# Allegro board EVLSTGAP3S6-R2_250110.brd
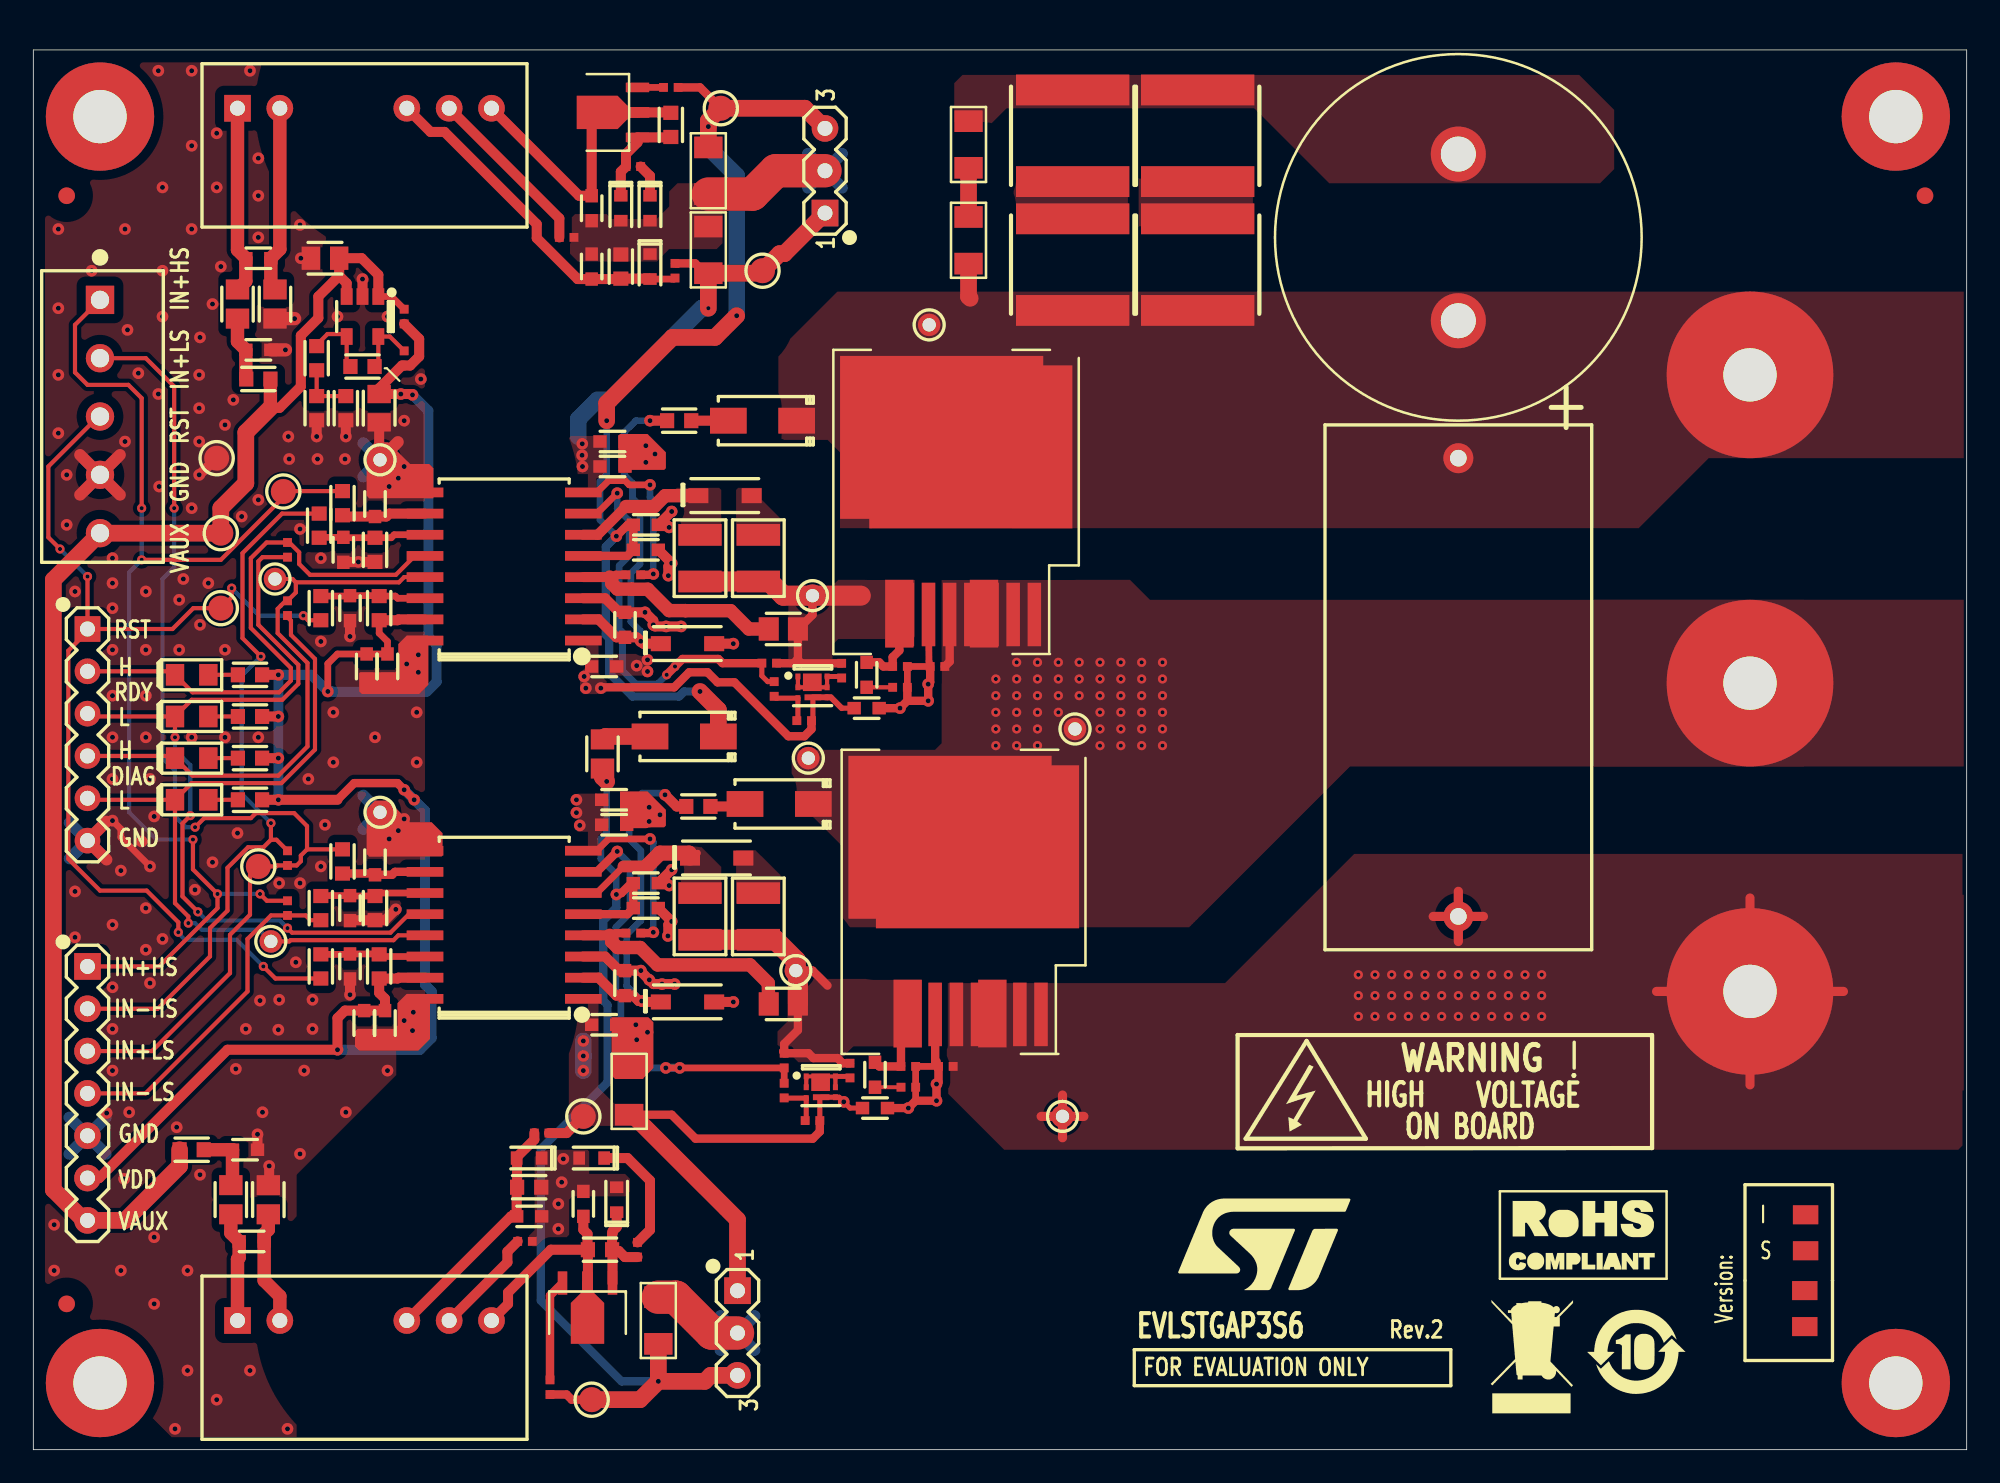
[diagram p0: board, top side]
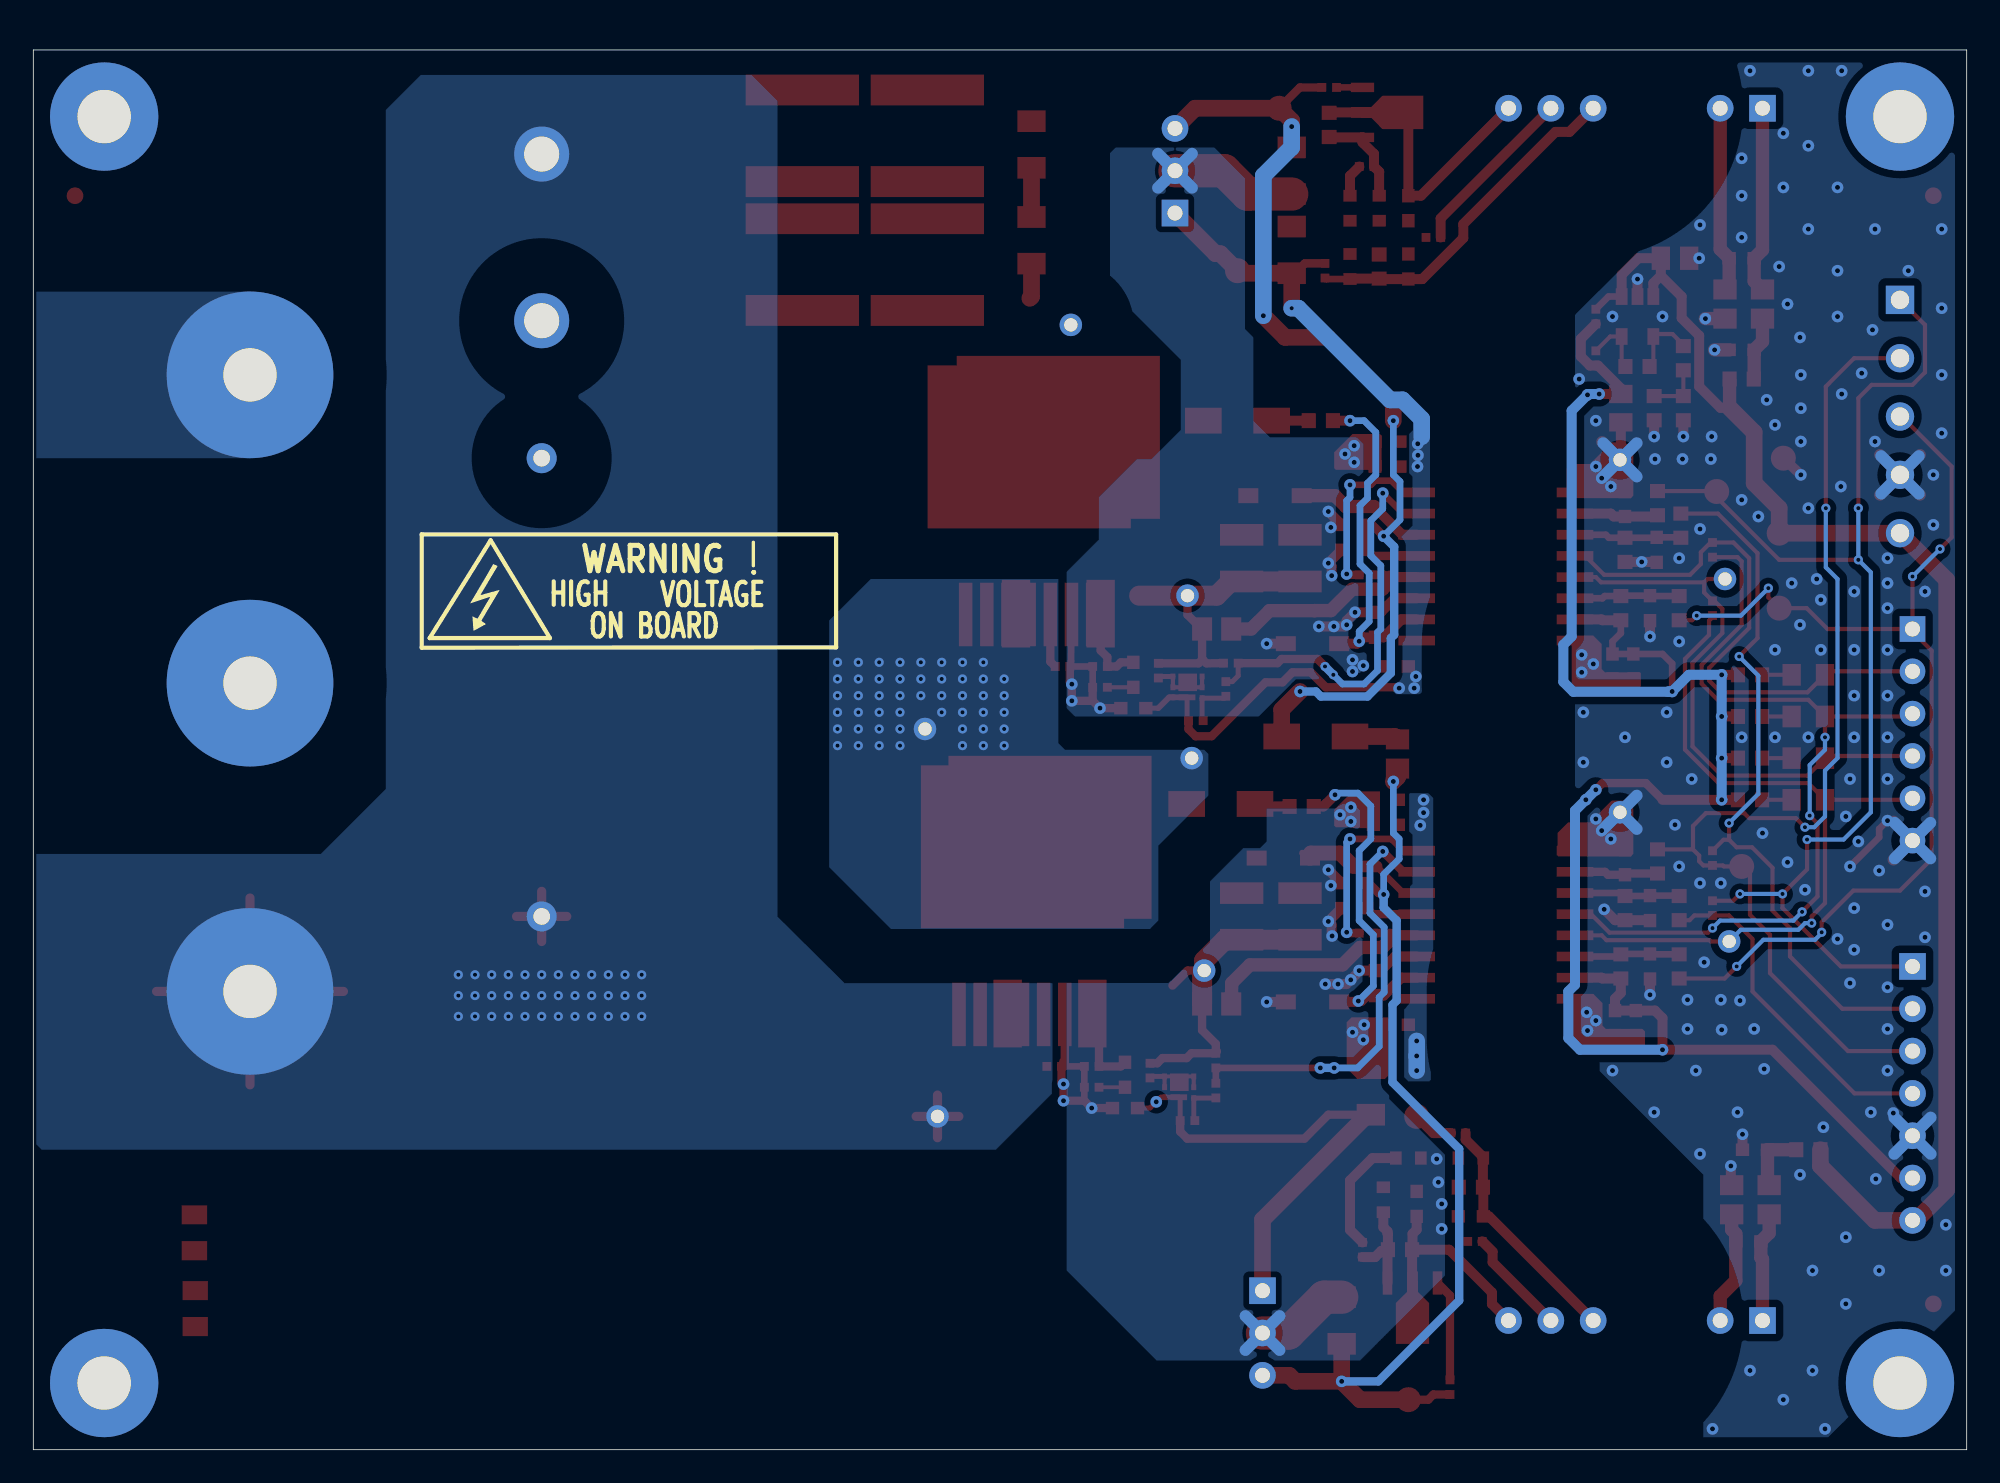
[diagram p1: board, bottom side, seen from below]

Outline 116 x 84 mm; copper layers: TOP, BOTTOM. Coordinates in mm from the lower left corner of the outline.
Outline path: 0,84 0,0 116,0 116,84 0,84

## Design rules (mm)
constraint set DEFAULT: min track width 0.25
net group GNDS: nets DIAG-H DIAG-L IN+_HS IN+_LS IN-_HS IN-_LS N16435324 N16435348 N16435442 N16459777 N16461917 N16462279 N16462299 N16609193 N16609281 N16609329 N16647913 N16647969 N16659631 N16659643 N16659681 N164429221 N164432121 N164593681 N164621091 NRST RDY-H RDY-L VAUX VDD
net group HIGH_SIDE: nets CLAMPDRV_H GNDISO_H N16436009 N16436033 N16436085 N16436375 N16436395 N16449698 N16450369 N16450393 N16606674 N16623492 N16681091 N16706479 N16716595 OUT VH_H VL_H
net group HV: nets HV
net group LOW_SIDE: nets CLAMPDRV_L GNDISO_L GNDPWR N16454045 N16454215 N16454235 N16604212 N16620609 N16659533 N16659557 N16659577 N16659585 N16659765 N16681015 N16706392 N16716713 VH_L
net group MIDDLE: nets N16440193 N16454073 N16617325 N16630507 N16636383 N16636469

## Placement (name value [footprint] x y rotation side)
C1  N.M.  [CAPE-R22H50-P100]  85.5 72.75 180 top
C2  N.M.  [C2225]  62.36 71.12 270 top
C3  N.M.  [C2225]  69.86 71.12 270 top
C4  3u3/1.1kV  [CAP-RAD-16X31_5H29_5P27_5]  85.5 45.75 90 top
C5  1uF/50V  [C0603]  36.75 55.5 180 top
C6  100nF/50V  [C0603]  36.75 54 180 top
C7  N.M.  [C2225]  62.36 78.85 270 top
C8  N.M.  [C2225]  69.86 78.85 270 top
C9  1uF/50V  [C0603]  34.75 60.5 0 top
C10  100nF/50V  [C0603]  34.75 59 0 top
C11  100pF/16V  [C0603]  20.5 56.75 270 top
C12  100pF/16V  [C0603]  18.6 54 90 top
C13  N.M.  [C0603]  50 46.5 90 top
C14  33pF/50V  [C0402]  36 52.5 180 top
C15  100pF/16V  [C0603]  19 50.5 90 top
C16  100nF/50V  [C0603]  34.25 47 0 top
C17  47pF/25V  [C0603]  35.5 49.5 270 top
C18  1uF/16V  [C0603]  20 47 90 top
C19  100nF/16V  [C0603]  21.25 47 90 top
C20  N.M.  [C0603]  50 44.5 0 top
C21  1uF/50V  [C0603]  36.75 34 180 top
C22  100nF/50V  [C0603]  36.75 32.5 180 top
C23  1uF/50V  [C0603]  34.85 39 0 top
C24  100nF/50V  [C0603]  34.85 37.5 0 top
C25  100pF/16V  [C0603]  20.5 35.25 270 top
C26  100pF/16V  [C0603]  19 32.5 90 top
C27  N.M.  [C0603]  50.5 22.5 90 top
C28  33pF/50V  [C0402]  36 31 180 top
C29  100pF/16V  [C0603]  19 29 90 top
C30  100nF/50V  [C0603]  34.25 25.5 0 top
C31  47pF/25V  [C0603]  35.5 28 270 top
C32  100nF/16V  [C0603]  21.1 25.6 90 top
C33  1uF/16V  [C0603]  19.85 25.6 90 top
C34  N.M.  [C0603]  50.5 20.5 0 top
C35  1uF/50V  [C0603]  33.5 74.5 90 top
C36  4.7uF/50V  [C1206]  40.5 76.75 90 top
C37  1uF/50V  [C0603]  13.5 71.5 0 top
C38  N.M.  [C0603]  13.5 66 0 top
C39  1uF/50V  [C0603]  33.5 71 90 top
C40  4.7uF/50V  [C1206]  40.5 72 90 top
C41  1uF/50V  [C0603]  33 14.75 270 top
C42  4.7uF/50V  [C1206]  37.5 7.75 270 top
C43  N.M.  [C0603]  12.7 18 0 top
C44  1uF/50V  [C0603]  13.1 12.5 0 top
C45  1uF/50V  [C0603]  29.75 14 0 top
C46  4.7uF/50V  [C1206]  35.75 21.5 90 top
C47  10uF/25V  [C0805]  17.5 71.5 0 top
C48  10uF/25V  [C0805]  20.75 62.5 90 top
D1  STPS2L40ZFY  [SOD-123]  41.5 57.25 0 top
D2  STTH112A  [DO-214AC]  43.75 61.75 180 top
D3  STPS2L40ZFY  [SOD-123]  39.25 48.37 0 top
D4  STTH112A  [DO-214AC]  39.05 42.8 180 top
D5  STPS2L40ZFY  [SOD-123]  41 35.5 0 top
D6  STTH112A  [DO-214AC]  44.75 38.75 180 top
D7  STPS2L40ZFY  [SOD-123]  39.25 26.87 0 top
D8  BZT585B15T  [SOD-523]  37 74.5 270 top
D9  BZT585B20T  [SOD-523]  35.25 74.5 270 top
D10  BZT52C4V7T  [SOD-523]  37 71 270 top
D11  BZT585B15T  [SOD-523]  33.5 17.5 180 top
D12  BZT585B20T  [SOD-523]  35 15 90 top
D13  BZT52C4V7T  [SOD-523]  29.75 17.5 180 top
FB1  BLM21AG471SN1  [R0805]  12.25 68.75 90 top
FB2  BLM21AG471SN1  [R0805]  14.5 68.75 90 top
FB3  BLM21AG471SN1  [R0805]  11.85 15 270 top
FB4  BLM21AG471SN1  [R0805]  14.1 15 270 top
GNDPWR  PAD_4_7D2_4MM  [PAD-10F3_2]  103 27.5 0 top
HV  PAD_4_7D2_4MM  [PAD-10F3_2]  103 64.5 0 top
J1  MORSV-350-5P_screw  [MORS_WR-TBL_691243110005_5P_3V5]  4 62 270 top
J2  STRIP 1x7  [STRIP_7V]  3.25 29 270 top
J3  STRIP 1x6  [STRIP_6V]  3.25 49.25 270 top
J4  STRIP 1x3  [STRIP_3V]  47.5 76.75 90 top
J5  STRIP 1x3  [STRIP_3V]  42.25 7 270 top
JR1  0  [R0603]  18.75 62.5 90 top
LED1  RED  [LED-0805]  9.5 46.5 0 top
LED2  RED  [LED-0805]  9.5 41.5 0 top
LED3  RED  [LED-0805]  9.5 44 0 top
LED4  RED  [LED-0805]  9.5 39 0 top
NOREF  -  []  -23.1 -77.75 0 top
NOREF#2  -  []  -70.5 -187.15 0 top
NOREF#3  -  []  0 84 0 top
NOREF#4  -  []  96.16 5.87 0 top
NOREF#5  -  []  0 0 90 top
NOREF#6  -  [unnamed#2]  4 80 0 top
NOREF#7  -  [unnamed#2]  4 4 0 top
NOREF#8  -  []  89.91 6.37 0 top
NOREF#9  -  [unnamed#3]  113.5 75.25 0 top
NOREF#10  -  []  73.75 12.25 0 top
NOREF#11  -  [unnamed#3]  2 8.75 0 top
NOREF#12  -  []  79.5 13.75 0 top
NOREF#13  -  [unnamed#2]  111.75 4 0 top
NOREF#14  -  [unnamed#2]  111.75 80 0 top
NOREF#15  -  []  -2 -57 0 top
NOREF#16  -  [unnamed#3]  2 75.25 0 top
NOREF#17  -  []  93 12.01 0 top
NOREF#18  -  []  79.06 54.7 180 bottom
OUT  PAD_4_7D2_4MM  [PAD-10F3_2]  103 46 0 top
Q1  N.M.  [H2PAK-7]  56.25 56.75 0 top
Q1A  STGB30H65DFB2  [D2PAK]  54.5 60.75 0 top
Q2  N.M.  [H2PAK-7]  56.65 32.75 0 top
Q2A  STGB30H65DFB2  [D2PAK]  55 36.75 0 top
Q3  STL7N6F7  [POWERFLAT6-2X2_P065-E]  46.75 45.75 270 top
Q4  STL7N6F7  [POWERFLAT6-2X2_P065-E]  47.25 21.75 270 top
Q5  2STF1360  [SOT-89]  36.25 80.25 180 top
Q6  2STF1360  [SOT-89]  33.25 10 270 top
R1  10M  [R1206]  56.11 72.58 270 top
R2  10M  [R1206]  56.11 78.33 270 top
R4  750  [R0603]  13 46.5 0 top
R5  100  [R0603]  18.55 56.8 90 top
R6  22  [R1210]  40 53.5 270 top
R7  100  [R0603]  17.15 55.45 270 top
R8  2R2  [R1210]  43.5 53.5 270 top
R9  N.M.  [R0603]  20.5 54 90 top
R10  10  [R0805]  45 49.25 0 top
R11  N.M.  [R0402]  15.25 35.5 270 top
R12  50K  [R0603]  20.75 50.5 270 top
R13  10k  [R0402]  52 47 180 top
R14  N.M.  [R0402]  52 45.75 180 top
R15  N.M.  [R0402]  54.25 47 180 top
R16  1K  [R0603]  38.75 61.75 180 top
R17  N.M.  [R0402]  15.25 32.5 270 top
R18  100  [R0603]  17.25 50.5 90 top
R19  750  [R0603]  13 41.5 0 top
R20  N.M.  [R0402]  15.25 50.5 90 top
R21  0  [R0402]  48.5 46.75 90 top
R22  N.M.  [R0402]  15.25 54 90 top
R23  N.M.  [R0805]  34.15 41.75 270 top
R24  2.2  [R0402]  44.45 45.65 270 top
R25  100k  [R0402]  46.25 43.75 0 top
R27  22  [R1210]  40 32 270 top
R28  750  [R0603]  13 44 0 top
R29  100  [R0603]  18.55 35.3 270 top
R30  100  [R0603]  17.25 32.5 90 top
R31  2R2  [R1210]  43.5 32 270 top
R32  N.M.  [R0603]  20.5 32.5 90 top
R33  10  [R0805]  45 26.75 0 top
R34  10k  [R0402]  52.5 23 180 top
R35  N.M.  [R0402]  54.75 23 180 top
R36  50K  [R0603]  20.75 29 270 top
R37  1K  [R0603]  39.9 38.6 0 top
R38  N.M.  [R0402]  52.5 21.75 180 top
R39  100  [R0603]  17.25 29 90 top
R40  750  [R0603]  13 39 0 top
R41  0  [R0402]  49 22.75 90 top
R42  2.2  [R0402]  45.05 21.55 270 top
R43  100k  [R0402]  46.75 19.75 0 top
R44  0  [R0402]  38.25 81.75 0 top
R45  1K  [R0603]  38.25 79.5 90 top
R46  0  [R0402]  36 77 180 top
R47  0  [R0603]  13.5 64.25 180 top
R48  N.M.  [R0402]  32 72.75 0 top
R49  N.M  [R0603]  35.25 71 90 top
R50  0  [R0402]  38.5 70.75 90 top
R51  0  [R0402]  31 3.75 270 top
R52  1K  [R0603]  34 12 180 top
R53  0  [R0402]  36.25 12 270 top
R54  0  [R0603]  9.5 18 0 top
R55  N.M.  [R0402]  29.5 12.5 0 top
R56  N.M  [R0603]  29.75 15.75 0 top
R57  0  [R0402]  30.5 19 0 top
R58  N.M.  [R0402]  22.25 68 270 top
R59  0  [R0402]  22.25 65.5 270 top
R60  4.7k  [R0603]  19.75 65 0 top
R61  1.47k  [R0603]  17 65.5 90 top
R62  1.18k  [R0603]  17 62.5 270 top
R63  N.M.  [R0402]  44.15 47.2 0 top
R64  N.M.  [R0402]  45.05 23.35 90 top
TP1  TP-diam1_27mm-Hole0_8mm  [TP-F0_8_PAD_1_35]  20.8 59.4 0 top
TP2  TP-diam1_27mm-Hole0_8mm  [TP-F0_8_PAD_1_35]  53.75 67.5 0 top
TP3  TP-diam1_27mm-Hole0_8mm  [TP-F0_8_PAD_1_35]  46.75 51.25 0 top
TP4  TP-diam1_27mm-Hole0_8mm  [TP-F0_8_PAD_1_35]  46.5 41.5 0 top
TP5  TP-diam1_27mm-Hole0_8mm  [TP-F0_8_PAD_1_35]  14.5 52.25 0 top
TP6  TP-diam1_27mm-Hole0_8mm  [TP-1_5]  15 57.5 270 top
TP7  TP-diam1_27mm-Hole0_8mm  [TP-1_5]  13.5 35 270 top
TP8  TP-diam1_27mm-Hole0_8mm  [TP-1_5]  11.25 50.5 0 top
TP9  TP-diam1_27mm-Hole0_8mm  [TP-1_5]  11 59.5 270 top
TP10  TP-diam1_27mm-Hole0_8mm  [TP-1_5]  11.25 55 270 top
TP11  TP-diam1_27mm-Hole0_8mm  [TP-F0_8_PAD_1_35]  20.8 38.25 0 top
TP12  TP-diam1_27mm-Hole0_8mm  [TP-F0_8_PAD_1_35]  62.5 43.25 0 top
TP13  TP-diam1_27mm-Hole0_8mm  [TP-F0_8_PAD_1_35]  45.75 28.75 0 top
TP14  TP-diam1_27mm-Hole0_8mm  [TP-F0_8_PAD_1_35]  61.75 20 0 top
TP15  TP-diam1_27mm-Hole0_8mm  [TP-F0_8_PAD_1_35]  14.25 30.5 0 top
TP16  TP-diam1_27mm-Hole0_8mm  [TP-1_5]  41.25 80.5 90 top
TP17  TP-diam1_27mm-Hole0_8mm  [TP-1_5]  43.75 70.75 90 top
TP18  TP-diam1_27mm-Hole0_8mm  [TP-1_5]  33.5 3 0 top
TP19  TP-diam1_27mm-Hole0_8mm  [TP-1_5]  33 20 270 top
U1  STGAP3S6I  [SO16_L10_4]  28.25 53 90 top
U2  STGAP3S6I  [SO16_L10_4]  28.25 31.5 90 top
U3  MGJ2D051515BSC  [CONV_MGJ2]  12.25 80.5 180 top
U4  MGJ2D051515BSC  [CONV_MGJ2]  12.25 7.75 180 top
U5  LDK220M-R  [SOT23-5L]  19.75 68 270 top

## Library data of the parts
C1 = C_EL-DIAM10
C2 C3 C7 C8 = C-2225
C4 = C-pitch15mm-13x18
C5 C6 C9-C13 C15-C27 C29-C35 C37 C39 C41 C44 C45 = C-0603
C14 C28 = C-0402
C36 C38 C40 C42 C43 C46 = CAPACITOR NON-POL
C47 C48 = C-0805
D1 D3 D5 D7 = STPS2L40ZFY_0
D2 D4 D6 = STTH112A_1
D8 D11 = BZT585B15T
D9 D12 = ZENER-SOD523
D10 D13 = BZT52C4V7T
FB1-FB4 = FERRITE-BEADS
GNDPWR HV OUT = PAD_4_7D2_4MM
J1 = MORSV-350-5P_screw
J2 = STRIP 1x7
J3 = STRIP 1x6
J4 J5 = STRIP 1x3
JR1 = JUMPER-R0603
LED1-LED4 = LED-0805-RED-WE
Q1 Q2 = SCTH40N120G2V7AG_1
Q1A Q2A = STGB50H65FB2_1
Q3 Q4 = STL7N6F7_0
Q5 Q6 = 2STF1360_0
R1 R2 = R-1206
R4 R5 R7 R9 R12 R16 R18 R19 R28-R30 R32 R36 R37 R39 R40 R60-R62 = R-0603
R6 R8 R27 R31 = R-1210
R10 R33 = R-0805
R11 R13-R15 R17 R20-R22 R24 R25 R34 R35 R38 R41-R44 R46 R48 R50 R51 R53 R55 R57-R59 R63 R64 = R-0402
R23 R45 R47 R49 R52 R54 R56 = R
TP1-TP19 = TP-diam1_27mm-Hole0_8mm
U1 U2 = STGAP3S1_6
U3 U4 = MGJ2D051515BSC
U5 = LDK220M-R

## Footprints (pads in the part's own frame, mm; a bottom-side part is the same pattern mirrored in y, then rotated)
C0402
  rect 0.53x0.53 smd: 1(-0.44,0) 2(0.44,0)
C0603
  rect 0.8x0.75 smd: 1(-0.75,0) 2(0.75,0)
C0805
  rect 1.1x1.4 smd: 1(-0.85,0) 2(0.85,0)
C1206
  rect 1.3x1.7 smd: 1(-1.4,0) 2(1.4,0)
C2225
  rect 1.85x6.8 smd: 1(-2.75,0) 2(2.75,0)
CAP-RAD-16X31_5H29_5P27_5
  round 1.8 hole 1: 1(-13.75,0) 2(13.75,0)
CAPE-R22H50-P100
  round 3.302 hole 2.1: 1(0,5) 2(0,-5)
CONV_MGJ2
  rect 1.6x1.6 hole 0.9: 1(0,0)
  round 1.6 hole 0.9: 2(-2.54,0) 5(-10.16,0) 6(-12.7,0) 7(-15.24,0)
D2PAK
  rect 1.702x4.064 smd: 1(-2.54,-10.58) 3(2.54,-10.58)
  rect 12.192x9.779 smd: 4(0,0)
DO-214AC
  rect 2.2x1.55 smd: 1(-2.05,0) 2(2.05,0)
H2PAK-7
  rect 0.813x3.81 smd: 1(-3.81,-6.629) 2(-2.54,-6.629) 3(-1.27,-6.629) 4(0,-6.629) 5(1.27,-6.629) 6(2.54,-6.629) 7(3.81,-6.629)
  rect 12.192x9.779 smd: 8(0,3.429)
LED-0805
  rect 1.1x1.3 smd: 1(-1,0) 2(1,0)
MORS_WR-TBL_691243110005_5P_3V5
  rect 1.7x1.7 hole 1.1: 1(-7,0)
  round 1.7 hole 1.1: 2(-3.5,0) 3(0,0) 4(3.5,0) 5(7,0)
PAD-10F3_2
  round 10 hole 3.2: 1(0,0)
POWERFLAT6-2X2_P065-E
  rect 0.35x0.3 smd: 1(-0.65,-0.875) 2(0,-0.875) 3(0.65,-0.875) 4(0.6,0.875) 5(0,0.875) 6(-0.65,0.875)
  rect 1.05x1.12 smd: 7(-0.3,-0.012)
  rect 0.35x1 smd: 8(0.6,0.025)
R0402
  rect 0.53x0.53 smd: 1(-0.44,0) 2(0.44,0)
R0603
  rect 0.85x0.9 smd: 1(-0.725,0) 2(0.725,0)
R0805
  rect 1.2x1.4 smd: 1(-0.875,0) 2(0.875,0)
R1206
  rect 1.3x1.7 smd: 1(-1.4,0) 2(1.4,0)
R1210
  rect 1.3x2.6 smd: 1(-1.4,0) 2(1.4,0)
SO16_L10_4
  rect 0.58x2.2 smd: 1(-4.445,-4.75) 2(-3.175,-4.75) 3(-1.905,-4.75) 4(-0.635,-4.75) 5(0.635,-4.75) 6(1.905,-4.75) 7(3.175,-4.75) 8(4.445,-4.75) 9(4.445,4.75) 10(3.175,4.75) 11(1.905,4.75) 12(0.635,4.75) 13(-0.635,4.75) 14(-1.905,4.75) 15(-3.175,4.75) 16(-4.445,4.75)
SOD-123
  rect 1.2x0.9 smd: 1(-1.6,0) 2(1.6,0)
SOD-523
  rect 0.7x0.8 smd: 1(-0.75,0) 2(0.75,0)
SOT23-5L
  rect 1x0.71 smd: 1(-1.2,0.95) 2(-1.2,0) 3(-1.2,-0.95) 4(1.2,-0.95) 5(1.2,0.95)
SOT-89
  rect 1.4x0.57 smd: 1(0,1.5) 3(0,-1.5)
  rect 1.4x0.65 smd: 2(0,0)
STRIP_3V
  rect 1.6x1.6 hole 0.9: 1(-2.54,0)
  round 1.6 hole 0.9: 2(0,0) 3(2.54,0)
STRIP_6V
  rect 1.54x1.54 hole 0.9: 1(0,0)
  round 1.54 hole 0.9: 2(2.54,0) 3(5.08,0) 4(7.62,0) 5(10.16,0) 6(12.7,0)
STRIP_7V
  rect 1.6x1.6 hole 0.9: 1(0,0)
  round 1.6 hole 0.9: 2(2.54,0) 3(5.08,0) 4(7.62,0) 5(10.16,0) 6(12.7,0) 7(15.24,0)
TP-1_5
  round 1.5 smd: 1(0,0)
TP-F0_8_PAD_1_35
  round 1.35 hole 0.8: 1(0,0)
unnamed#2
  round 6.5 hole 3.2: 1(0,0)
unnamed#3
  round 1 smd: (0,0)

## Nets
GND_SIGNAL: C11.1 C12.1 C15.1 C18.1 C19.1 C25.1 C26.1 C29.1 C32.1 C33.1 C38.2 C43.2 C47.1 C48.1 FB2.1 FB4.1 J1.4 J2.5 J3.6 JR1.1 R9.1 R32.1 R62.2 TP1.1 TP9.1 TP11.1 U1.9 U1.16 U2.9 U2.16 U5.2
GNDISO_H: C5.1 C6.1 C9.2 C10.2 C16.2 C17.1 C20.2 C35.1 C36.1 C39.2 C40.2 D3.2 D8.2 D9.2 D10.1(CATHODE) J4.2 Q1.2 R13.1 R14.1 R15.2 R48.2 R49.2 U1.3
GNDISO_L: C21.1 C22.1 C23.2 C24.2 C30.2 C31.1 C34.2 C41.1 C42.1 C45.2 C46.2 D7.2 D11.2 D12.2 D13.1(CATHODE) J5.2 Q2.2 R34.1 R35.2 R38.1 R55.2 R56.2 U2.3
GNDPWR: C1.2 C4.1 C7.1 C8.1 GNDPWR.1 Q2.3 Q2.4 Q2.5 Q2.6 Q2.7(SOURCE#7) Q2A.3(S) R2.1 R35.1 TP14.1
VDD: C18.2 C19.2 C32.2 C33.2 C48.2 J2.6 R4.2 R12.2 R19.2 R28.2 R36.2 R40.2 R58.2 R59.2 U1.15 U2.15
CLAMPDRV_H: R24.1 R63.1 U1.7
CLAMPDRV_L: R42.1 R64.1 U2.7
DIAG-H: J3.4 LED2.1 R20.2 TP5.1 U1.13
DIAG-L: J3.5 LED4.1 R20.1 TP15.1 U2.13
G_HS: C13.2 Q1.1 Q1A.1 R6.2 R8.2 R10.2 R13.2 R21.2 R63.2 TP3.1
G_LS: C27.2 Q2.1 Q2A.1 R27.2 R31.2 R33.2 R34.2 R41.2 R64.2 TP13.1
HV: C1.1(POS) C2.2 C3.2 C4.2 D2.1 HV.1 Q1.8 Q1A.4 R1.2 TP2.1
IN+_HS: J1.1 J2.1 R5.2 R17.1 TP6.1
IN+_LS: J1.2 J2.3 R11.2 R29.1 TP7.1
IN-_HS: J2.2 R7.1 R11.1
IN-_LS: J2.4 R17.2 R30.1
NRST: J1.3 J3.1 R18.1 R39.1 TP8.1
OUT: D6.1 OUT.1 Q1.3 Q1.4 Q1.5 Q1.6 Q1.7(SOURCE#7) Q1A.3(S) Q2.8 Q2A.4 R15.1 TP4.1 TP12.1
RDY-H: J3.2 LED1.1 R22.2 U1.12
RDY-L: J3.3 LED3.1 R22.1 U2.12
VAUX: C47.2 J1.5 J2.7 R47.1 R54.1 R58.1 TP10.1 U5.1 U5.3
VH_H: C5.2 C6.2 C36.2 D4.1 J4.3 R44.2 TP16.1 U1.5
VH_L: C21.2 C22.2 C42.2 J5.3 R23.2 R51.2 TP18.1 U2.5
VL_H: C9.1 C10.1 C14.1 C16.1 C20.1 C40.1 J4.1 Q3.4 Q3.8(S#8) R25.2 R50.2 TP17.1 U1.1 U1.8(VL#8)
VL_L: C23.1 C24.1 C28.1 C30.1 C34.1 C46.1 J5.1 Q4.4 Q4.8(S#8) R43.2 R57.2 TP19.1 U2.1 U2.8(VL#8)
N16435324: C37.1 FB1.2 U3.1
N16435348: C37.2 FB2.2 U3.2
N16435442: C38.1 FB1.1 R47.2
N16436009: D9.1(CATHODE) Q5.1 R45.1 R46.2
N16436033: C39.1 D10.2 R49.1 R50.1 U3.5
N16436085: D8.1(CATHODE) R46.1
N16436375: C35.2 Q5.2 R45.2 U3.7
N16436395: Q5.3(E) R44.1
N16440193: R1.1 R2.2
N16449698: C17.2 D3.1 R16.2 U1.2
N16450369: D1.1 R6.1 U1.6
N16450393: D1.2 R8.1
N16454045: C31.2 D7.1 R37.1 U2.2
N16454073: D6.2 R37.2
N16454215: D5.1 R27.1 U2.6
N16454235: D5.2 R31.1
N16459777: C25.2 R29.2 U2.10
N16461917: C15.2 R12.1 R18.2 U1.14
N16462279: C11.2 R5.1 U1.10
N16462299: C12.2 R7.2 R9.2 U1.11
N16604212: Q4.3 R42.2 R43.1
N16606674: Q3.3 R24.2 R25.1
N16609193: R59.1 R60.2 U5.5(VOUT)
N16609281: R60.1 R61.2 U5.4
N16609329: JR1.2 R61.1 R62.1
N16617325: D2.2 R16.1
N16620609: C27.1 R38.2
N16623492: C13.1 R14.2
N16630507: D4.2 R23.1
N16636383: C2.1 C7.2
N16636469: C3.1 C8.2
N16647913: C26.2 R30.2 R32.2 U2.11
N16647969: C29.2 R36.1 R39.2 U2.14
N16659533: C41.2 Q6.2 R52.2 U4.7
N16659557: Q6.3(E) R51.1
N16659577: D12.1(CATHODE) Q6.1 R52.1 R53.2
N16659585: D11.1(CATHODE) R53.1
N16659631: C43.1 FB3.1 R54.2
N16659643: C44.1 FB3.2 U4.1
N16659681: C44.2 FB4.2 U4.2
N16659765: C45.1 D13.2 R56.1 R57.1 U4.5
N16681015: Q4.1 Q4.2 Q4.5 Q4.6 Q4.7 R41.1
N16681091: Q3.1 Q3.2 Q3.5 Q3.6 Q3.7 R21.1
N16706392: C28.2 R33.1 U2.4
N16706479: C14.2 R10.1 U1.4
N16716595: R48.1 U3.6(0V)
N16716713: R55.1 U4.6(0V)
N164429221: LED2.2 R19.1
N164432121: LED4.2 R40.1
N164593681: LED3.2 R28.1
N164621091: LED1.2 R4.1

Pads without a net: NOREF#6 1; NOREF#7 1; NOREF#13 1; NOREF#14 1

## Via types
v1: diameter 0.55, hole 0.25, TOP to BOTTOM, 107 vias
v2: diameter 0.7, hole 0.3, TOP to BOTTOM, 236 vias

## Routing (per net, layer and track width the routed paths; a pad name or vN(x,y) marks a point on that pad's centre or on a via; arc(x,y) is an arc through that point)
GND_SIGNAL: length 74.1
  TOP w0.4: v2(7,35) 5.25,36.75 5.25,37.25 v2(4.75,37.75)
  TOP w0.5: U2.9 20.55,35.95 C25.1 20.5,37.95 TP11.1
  TOP w0.6: C48.1 20.75,59.45 TP1.1 20.5,59.1 C11.1 20.55,57.45 U1.9 ; C12.1 19.02,53.27 v2(19.5,53.27) R9.1 ; R62.2 v2(17,60.8) ; U5.2 v2(19.75,70.25) ; JR1.1 v2(18.75,60.8) ; C29.1 v2(19,27.3) ; v2(14.15,17.02) 14.15,15.93 FB4.1 ; C47.1 v2(16.05,71.5) ; C26.1 19.02,31.77 R32.1 21.1,31.77 v2(21.75,32.43) ; C43.2 v2(13.45,18.93) ; C15.1 v2(19,48.8) ; TP9.1 v2(9.95,58.5)
  TOP w0.7: J1.4 5.2,59.7 ; J1.4 2.8,57.3 ; J1.4 2.8,59.7 ; J1.4 5.2,57.3 ; 4.39,35.41 J3.6 4.39,37.69 ; 21.88,58.32 TP1.1 21.88,60.48
  TOP w0.8: C38.2 v2(15.12,66) ; FB2.1 v2(15.68,67.88)
  BOTTOM w0.7: TP1.1 21.81,60.41 ; TP1.1 21.81,58.39 ; TP1.1 19.79,60.41 ; TP1.1 19.79,58.39 ; 19.79,39.26 TP11.1 ; TP11.1 21.81,37.24 ; TP11.1 19.79,37.24 ; 2.16,19.93 J2.5 ; J2.5 4.34,17.75 ; J2.5 4.34,19.93 ; J2.5 2.16,17.75 ; 2.18,35.48 J3.6 ; J3.6 4.32,35.48 ; J3.6 2.18,37.62 ; J3.6 4.32,37.62 ; J1.4 5.13,57.37 ; J1.4 2.87,57.37 ; J1.4 5.13,59.63 ; J1.4 2.87,59.63
  vias: v2(1.25,13.5) v2(1.25,10.75) v2(1.5,73.25) v2(1.5,68.5) v2(1.5,64.5) v2(1.5,61) v2(2,58.5) v2(2,55.5) v2(2.5,51.5) v2(2.5,33.5) v2(2.5,30.75) v2(3.5,70.75) v2(4.4,20.2) v2(4.75,53.5) v2(4.75,52) v2(4.75,50.5) v2(4.75,48) v2(4.75,45.25) v2(4.75,42.75) v2(4.75,40.25) v2(4.75,31.5) v2(4.75,27.75) v2(4.75,25.25) v2(4.75,22.75) v2(5.25,34.75) v2(5.25,10.75) v2(5.5,73.25) v2(5.5,60.5) v2(5.45,16.25) v2(5.65,67.2) v2(5.75,20.25) v2(6.3,64.6) v2(6.5,36.5) v2(6.75,51.5) v2(6.75,48) v2(6.75,45.25) v2(6.75,42.75) v2(6.75,32.5) v2(6.75,30) v2(7,40.25) v2(7,28) v2(7.25,38) v2(7.25,12.75) v2(7.25,8.75) v2(7.5,82.75) v2(7.5,63.35) v2(7.55,57.8) v2(7.75,75.75) v2(7.75,70.75) v2(7.75,68) v2(7.75,30.65) v2(8.5,1.25) v2(8.6,19.35) v2(8.75,51) v2(8.75,48) v2(9,52.25) v2(9.25,10.75) v2(9.25,4.75) v2(9.5,82.75) v2(9.5,78.25) v2(9.5,73.25) v2(9.5,56.5) v2(9.5,42.75) v2(9.7,33.6) v2(9.95,64.5) v2(9.95,62.5) v2(9.95,60.5) v2(10,66.75) v2(10,49.5) v2(10,16.5) v2(10.5,52) v2(10.75,68.75) v2(10.75,35.25) v2(11,79) v2(11,75.75) v2(11,3) v2(11.25,71) v2(11.5,61.5) v2(11.5,48) v2(11.5,42.75) v2(12,63) v2(12.25,37) v2(12.15,22.85) v2(12.5,56) v2(12.75,25.25) v2(13,82.75) v2(13,4.75) v2(13.5,77.5) v2(13.5,75.25) v2(13.5,72.75) v2(13.5,57) v2(13.5,42.75) v2(13.6,26.95) v2(13.75,20.25) v2(14.7,25.2) v2(14.75,34) v2(14.75,27) v2(15.25,1.25) v2(15.3,60.8) v2(15.35,59.45) v2(15.75,29.25) v2(16,73.5) v2(16,55.25) v2(16,34) v2(16,17.75) v2(16.25,22.75) v2(16.5,40.25) v2(16.75,27) v2(16.75,25.25) v2(17.05,59.45) v2(17.25,53.5) v2(17.25,48.5) v2(17.25,35) v2(17.5,37.5) v2(18,44.25) v2(18,41.25) v2(18.25,68) v2(18.7,59.45) v2(18.75,20.25) v2(20.5,42.75) v2(21.25,68) v2(21.25,22.75) v2(21.35,57.8) v2(21.35,36.65) v2(21.9,58.3) v2(21.9,37.15) v2(22.25,61.75) v2(22.25,59) v2(22.25,37.85) v2(22.25,25.75) v2(22.4,47.15) v2(22.8,26.25) v2(22.75,25.15) v2(23,44.25) v2(23,41.25) v2(23.1,47.7) v2(23.1,46.65) v2(23.25,64.25)
GNDISO_H: length 36.8
  TOP w0.4: Q1.2 53.74,47.32 R15.2 R13.1 R14.1
  TOP w0.5: R15.2 53.81,46.06 v2(53.69,45.94) v2(53.69,44.94) 52.44,44.94 ; 52.44,44.94 R14.1 ; 52.44,44.94 v2(52,44.5) C20.2
  TOP w0.6: v2(42,48.37) D3.2 ; U1.3 34.3,51.09 35.15,50.25 C17.1 v2(36.7,50.25) 37.2,49.75 v2(37.2,49.5) 37.3,49.4 v2(37.97,49.4) v2(38.87,49.4) ; v2(38.1,52.45) 38.1,53 v2(38.3,53.2) C6.1 ; v2(38.15,55.35) 38,55.5 C5.1 v2(38.3,56.3)
  TOP w2: C36.1 43.15,75.35 44.55,76.75 J4.2
  BOTTOM w0.7: 46.48,75.73 J4.2 ; J4.2 48.52,75.73 ; J4.2 48.52,77.77 ; J4.2 46.48,77.77
  vias: v2(36.2,47.05) v2(36.75,60.25) v2(36.75,59.25) v2(36.85,47.4) v2(36.85,46.7) v2(37.3,59.75)
GNDISO_L: length 39.3
  TOP w0.4: 52.94,23 R38.1 52.94,20.94 ; 52.94,23 52.94,23 R35.2 54.24,23.32 ; 52.94,23 R34.1 ; C24.2 36.75,37.5 v2(36.95,37.7) ; v2(36.85,25.05) 36.4,25.5 v2(36.15,25.5) 36.2,25.45 v2(36.2,24.6)
  TOP w0.5: C34.2 v2(52.5,20.5) 52.94,20.94 v2(54.19,20.94) v2(54.19,21.94) 54.31,22.06 R35.2 54.11,23.2 Q2.2
  TOP w0.6: v2(38.15,33.85) 38,34 C21.1 v2(38.3,34.8) ; C22.1 v2(38.3,31.7) 38.1,31.5 38.1,30.85 v2(38.08,30.83) ; C30.2 v2(36.15,25.5) ; v2(38.48,27.94) v2(37.72,27.94) 37.21,27.94 v2(36.96,28.19) 36.45,28.7 v2(36.45,28.75) C31.1 35.15,28.75 34.3,29.59 U2.3 ; v2(42,26.87) D7.2
  TOP w2: C42.1 38.55,9.15 40.7,7 J5.2
  BOTTOM w0.7: 41.23,5.98 J5.2 ; J5.2 43.27,5.98 ; J5.2 41.23,8.02 ; J5.2 43.27,8.02
  vias: v2(31.5,14.75) v2(31.5,13.25) v2(31.7,16.05) v2(31.8,17.45) v2(36.95,38.55) v2(37.6,38.1)
GNDPWR: length 33.6
  TOP w0.55: 83.99,32 C4.1 ; C4.1 87.01,32 ; C4.1 85.5,30.49 ; C4.1 85.5,33.51 ; GNDPWR.1 103,33.11 ; GNDPWR.1 97.39,27.5 ; GNDPWR.1 103,21.89 ; GNDPWR.1 108.61,27.5 ; TP14.1 61.75,21.28 ; TP14.1 61.75,18.72 ; TP14.1 63.03,20 ; TP14.1 60.47,20
  vias: v1(79.5,28.5) v1(79.5,27.25) v1(79.5,26) v1(80.5,28.5) v1(80.5,27.25) v1(80.5,26) v1(81.5,28.5) v1(81.5,27.25) v1(81.5,26) v1(82.5,28.5) v1(82.5,27.25) v1(82.5,26) v1(83.5,28.5) v1(83.5,27.25) v1(83.5,26) v1(84.5,28.5) v1(84.5,27.25) v1(84.5,26) v1(85.5,28.5) v1(85.5,27.25) v1(85.5,26) v1(86.5,28.5) v1(86.5,27.25) v1(86.5,26) v1(87.5,28.5) v1(87.5,27.25) v1(87.5,26) v1(88.5,28.5) v1(88.5,27.25) v1(88.5,26) v1(89.5,28.5) v1(89.5,27.25) v1(89.5,26) v1(90.5,28.5) v1(90.5,27.25) v1(90.5,26)
VDD: length 117
  TOP w0.4: R12.2 20.75,49 21.25,48.5 C19.2 C18.2 18.25,47.75 17.67,47.17 v2(17.67,45.5)
  TOP w0.5: v2(22.85,39) v2(22.25,39.6) 21.85,40 19.25,40 18.25,39
  TOP w0.6: R28.2 v2(14.7,44) ; U2.15 21.91,28.32 21.86,28.27 R36.2 20.75,27.41 21.1,27.06 C32.2 C33.2 18.7,26.35 18.25,25.9 v2(18.25,24) 11.65,24 3.95,16.3 J2.6 ; U1.15 21.91,49.83 21.86,49.77 R12.2 ; R40.2 v2(14.7,39) 18.25,39 ; R58.2 23.15,66.66 23.15,65.6 22.61,65.06 R59.2 22.12,65.06 20.75,63.69 C48.2 v2(22.05,63.35) 22.7,63.35 v2(22.75,63.3) ; R19.2 v2(14.7,41.5) ; R4.2 v2(14.7,46.5)
  BOTTOM w0.6: v2(18.25,24) 23.2,24 23.9,24.7 23.9,27.5 23.5,27.9 23.5,38.35 v2(22.85,39) v2(22.25,39.6) ; v2(22.05,63.35) 22.7,63.35 v2(22.75,63.3) 23.7,62.35 23.7,48.8 24.2,48.3 24.2,46.08 23.6,45.48 17.92,45.48 17.9,45.5 v2(17.67,45.5) 16.67,46.5 v2(14.7,46.5) v2(14.7,44) v2(14.7,41.5) v2(14.7,39)
CLAMPDRV_H: length 25.6
  TOP w0.3: R63.1 43.71,46.44 44.06,46.09 R24.1
  TOP w0.4: U1.7 33.81,56.17 v2(35.03,57.4)
  TOP w0.5: v1(38,46.5) v1(38.5,47) 38.95,47.45 41.1,47.45 41.35,47.2 R63.1
  BOTTOM w0.4: v1(38,46.5) 37.45,45.95 36.15,45.95 35.35,46.75 35.35,49.05 35.15,49.25 35.15,53.05 35.75,53.65 35.75,55.75 35.03,56.47 v2(35.03,57.4)
  BOTTOM w0.5: v1(38.5,47) v1(38,46.5)
CLAMPDRV_L: length 27.1
  TOP w0.4: v2(37.95,22.91) v2(38.78,22.91) R64.1 R42.1
  TOP w0.5: v2(35.03,35.9) 33.81,34.67 U2.7
  BOTTOM w0.4: v2(37.95,22.91) 36.54,22.91 35.25,24.2 35.25,27.15 34.95,27.45 34.95,31.35 35.8,32.2 35.8,35.13 v2(35.03,35.9)
  BOTTOM w0.5: v2(38.78,22.91) v2(37.95,22.91)
DIAG-H: length 34.7
  TOP w0.25: 15.75,52.05 15.75,51.44 R20.2 15.14,50.94 14.85,50.65 14.66,50.46 14.66,49 16.45,47.21 16.45,42.2 14.7,40.45 9.55,40.45 LED2.1 8.37,41.63 J3.4 ; 15.75,52.05 15.55,52.25 TP5.1 ; 15.75,52.05 21.94,52.05 22.25,52.37 U1.13
DIAG-L: length 46.2
  TOP w0.25: TP15.1 15.36,30.5 15.43,30.57 21.61,30.57 21.9,30.86 U2.13 ; LED4.1 9.5,40 14.89,40 16.9,42.01 16.9,47.45 15.46,48.89 15.46,49.75 15.25,49.96 R20.1 ; LED4.1 3.34,39 J3.5 ; LED4.1 8.5,32.8 9.3,32 v1(9.3,31.6)
  BOTTOM w0.25: TP15.1 13.55,31.2 10.1,31.2 9.7,31.6 v1(9.3,31.6)
G_HS: length 24.3
  TOP w0.25: 51.5,47.25 51.5,47.5 51.56,47.56 ; Q1A.1 51.96,49.64
  TOP w0.5: 45.85,47.43 46.09,47.19 R21.2 ; 45.85,47.43 45.61,47.19 R63.2 ; 45.85,47.43 45.88,47.45 R10.2 45.9,49.25 46.75,50.1 TP3.1 ; Q1.1 51.96,49.64 51.96,47.96 51.56,47.56 R13.2 51,47 50.75,47.25 C13.2
  TOP w1.2: 49.65,51.25 TP3.1 45,51.25 44.15,52.1 R8.2 R6.2
G_LS: length 23.7
  TOP w0.5: 47.65,27.85 46.75,28.75 TP13.1 ; R41.2 48.56,23.19 48.25,23.5 46.8,23.5 46.51,23.79 R64.2 45,23.9 45.05,23.95 45.05,24.35 45.88,25.18 R33.2 ; C27.2 50.75,23 R34.2 52.06,25.77 Q2A.1
  TOP w1.2: R33.2 45.88,28.62 TP13.1 45.75,29.35 44.5,30.6 R31.2 R27.2
HV: length 2.1
  TOP w1: R1.2 56.11,69.19 56.21,69.09
IN+_HS: length 71.6
  TOP w0.25: v1(6.5,53.4) 11.25,53.4 15,57.15 TP6.1 15.03,57.52 R5.2 ; R17.1 14.01,32.94 v1(13.6,33.35) ; J2.1 7.55,29 11.05,32.5 v1(11.05,33.35) 9.58,34.82 v1(9.58,36.62) ; v1(6.5,56.5) 6.5,63.1 5.7,63.9 3.25,63.9 2.5,64.65 2.5,67.5 J1.1
  BOTTOM w0.25: v1(11.05,33.35) v1(13.6,33.35) ; v1(9.58,36.62) 7.38,36.62 5.75,38.25 5.75,52.65 v1(6.5,53.4) v1(6.5,56.5)
IN+_LS: length 65.1
  TOP w0.25: v1(9.71,37.35) 10.25,37.9 13.05,37.9 13.35,38.2 15.65,38.2 16.42,37.42 16.42,36.02 ; 16.42,36.02 R29.1 ; 16.42,36.02 16.05,35.65 16.05,35.31 15.8,35.06 R11.2 14.63,35.06 14.57,35 TP7.1 13,34.5 13,32.1 11.8,30.9 11.8,28.6 7.12,23.92 J2.3 ; J1.2 6.75,65.5 8.45,63.8 v1(8.45,56.5)
  BOTTOM w0.25: v1(9.71,37.35) 9.15,37.35 8.5,38 8.5,40.75 7.75,41.5 7.75,52.25 8.45,52.95 v1(8.45,56.5)
IN-_HS: length 43.4
  TOP w0.25: 14.26,36.6 v1(14.26,37.6) ; 14.26,36.6 14.59,36.6 R11.1 ; 14.26,36.6 13.8,36.15 12.88,36.15 11.65,34.92 11.65,32.35 10.6,31.3 10.6,29.6 7.46,26.46 J2.2 ; R7.1 14.93,56.17 12.55,53.8 12.55,48.7 v1(13.65,47.6)
  BOTTOM w0.25: v1(14.26,37.6) 12.5,39.35 12.5,46.45 v1(13.65,47.6)
IN-_LS: length 20.4
  TOP w0.25: R30.1 16.62,31.77 16.34,32.06 R17.2 14.26,32.06 12.85,30.65 12.85,27.5 6.73,21.38 J2.4
NRST: length 64
  TOP w0.25: J1.3 3.9,62 0.9,59 0.9,54.75 v1(1.6,54.05) ; v1(16.2,50.05) 16.48,49.77 R18.1 ; J3.1 8.35,49.25 9.6,50.5 TP8.1 11.9,51.15 v1(11.9,51.7) ; J3.1 3.25,49.1 2.1,47.95 2.1,35.45 4,33.55 6.8,33.55 8.7,31.65 v1(8.7,31.05) ; J3.1 v1(3.25,52.4) ; R39.1 14.53,28.27 v1(13.8,29)
  BOTTOM w0.25: v1(16.2,50.05) 13.55,50.05 v1(11.9,51.7) ; v1(1.6,54.05) v1(3.25,52.4) ; v1(13.8,29) 12.2,30.6 9.1,30.6 8.7,31 v1(8.7,31.05)
OUT: length 3.2
  TOP w0.5: R15.1 54.98,47.29 Q1.3
  vias: v1(57.75,46.25) v1(57.75,45.25) v1(57.75,44.25) v1(57.75,43.25) v1(57.75,42.25) v1(59,47.25) v1(59,46.25) v1(59,45.25) v1(59,44.25) v1(59,43.25) v1(59,42.25) v1(60.25,47.25) v1(60.25,46.25) v1(60.25,45.25) v1(60.25,44.25) v1(60.25,43.25) v1(60.25,42.25) v1(61.5,47.25) v1(61.5,46.25) v1(61.5,45.25) v1(61.5,44.25) v1(62.75,47.25) v1(62.75,46.25) v1(62.75,45.25) v1(64,47.25) v1(64,46.25) v1(64,45.25) v1(64,44.25) v1(64,43.25) v1(64,42.25) v1(65.25,47.25) v1(65.25,46.25) v1(65.25,45.25) v1(65.25,44.25) v1(65.25,43.25) v1(65.25,42.25) v1(66.5,47.25) v1(66.5,46.25) v1(66.5,45.25) v1(66.5,44.25) v1(66.5,43.25) v1(66.5,42.25) v1(67.75,47.25) v1(67.75,46.25) v1(67.75,45.25) v1(67.75,44.25) v1(67.75,43.25) v1(67.75,42.25)
RDY-H: length 33.9
  TOP w0.25: U1.12 22.89,53.63 21.75,52.5 16.6,52.5 15.95,53.15 15.95,53.85 15.36,54.44 R22.2 13.99,54.44 13.05,53.5 13.05,49.31 15.45,46.91 15.45,46.15 14.75,45.45 9.55,45.45 LED1.1 8.29,46.71 J3.2
RDY-L: length 51
  TOP w0.25: v1(9.88,32.27) 8.95,33.2 8.95,37.58 v1(9.42,38.05) ; v1(15.25,31.3) 15.53,31.02 21.43,31.02 22.54,32.13 U2.12 ; R22.1 13.75,53.56 13.5,53.31 13.5,49.5 15.9,47.1 15.9,45.96 14.94,45 9.5,45 LED3.1 ; J3.3 3.42,44 LED3.1 ; LED3.1 v1(8.5,42.75)
  BOTTOM w0.25: v1(9.88,32.27) 10.4,31.75 14.8,31.75 v1(15.25,31.3) ; v1(9.42,38.05) 9.42,41.08 8.5,42 v1(8.5,42.75)
VAUX: length 87.3
  TOP w0.4: U5.1 21.49,69.2 R58.1
  TOP w0.6: 14.22,62.52 14.77,62.52 16.05,63.8 16.05,66.86 17.1,67.91 17.1,69.2 18.35,70.45 ; 18.35,70.45 C47.2 19.7,71.5 20.7,70.5 U5.1 ; 18.35,70.45 18.8,70 U5.3
  TOP w0.8: 14.22,62.52 R47.1
  TOP w1: R54.1 8.78,17.02 5.51,13.76 J2.7 3.04,13.76 1.2,15.6 1.2,52.2 J1.5 TP10.1 11.25,56.5 12.75,58 12.75,61.05 14.22,62.52
VH_H: length 66.9
  TOP w0.5: TP16.1 40,81.75 R44.2 ; v2(34.98,54.82) 35.66,55.5 C5.2 C6.2 35.63,53.63 U1.5
  TOP w1: v2(34.4,61.75) 34.4,62.8 38.35,66.75 40.9,66.75 v2(42.2,68.05) ; J4.3 46.29,80.5 TP16.1 40.5,79.75 v2(40.5,79.4) C36.2 ; v2(40,45.5) 41.1,44.4 D4.1
  BOTTOM w0.4: v2(34.98,54.82) 34,55.8 34,58.1 34.4,58.5 v2(34.4,61.75)
  BOTTOM w0.5: v2(40,45.5) 39.05,45.5 38.75,45.2 35.95,45.2 34.55,46.6 34.55,48.7 34.35,48.9 34.35,54.19 v2(34.98,54.82)
  BOTTOM w1: v2(40.5,79.4) C36.2 42.2,76.45 v2(42.2,68.05)
VH_L: length 63.9
  TOP w0.5: TP18.1 32.3,3 32,3.31 R51.2 ; U2.5 35.63,32.13 C22.2 C21.2 35.88,34 35.28,33.4 35.06,33.4 v2(34.98,33.32)
  TOP w1: J5.3 40.65,4.46 40.28,4.1 v2(37.5,4.1) ; v2(37.5,4.1) 36.4,3 TP18.1 ; v2(37.5,4.1) C42.2 ; R23.2 34.15,40.35 v2(34.4,40.1)
  BOTTOM w0.4: v2(34.4,40.1) 34.4,37 34.05,36.65 34.05,35.45 34.98,34.52 v2(34.98,33.32)
  BOTTOM w0.5: v2(34.98,33.32) 34.98,32.53 34.2,31.75 34.2,26.95 34.45,26.7 34.45,22.05 30.45,18.05 30.45,8.95 35.3,4.1 v2(37.5,4.1)
VL_H: length 54.6
  TOP w0.3: C20.1 48.5,44.5 ; Q3.8 46.77,43.84 R25.2
  TOP w0.35: Q3.8 Q3.4 47.85,45.15 48.5,44.5
  TOP w0.4: U1.8 33.81,57.45 34.51,58.15 35.5,58.15 35.75,57.9 v2(37,57.9)
  TOP w0.5: R50.2 39.71,71.19 40.3,70.6 C40.1 ; R25.2 46.69,43.24 46.27,42.82 45.3,42.82 42.07,46.05 41.05,46.05 40.45,46.65 39.35,46.65 38.45,45.75 34.1,45.75 v2(34.05,45.7) ; v2(37.2,52.55) 37.15,52.5 C14.1
  TOP w1: v1(40.5,68.5) C40.1 43.6,70.6 TP17.1 44.77,71.77 45.06,71.77 J4.1
  BOTTOM w0.4: v2(37.2,52.55) 37.2,56.95 37,57.15 v2(37,57.9)
  BOTTOM w1: 32.7,60.79 32.7,61.85 33.85,63 34.6,63 40.1,68.5 v1(40.5,68.5)
  vias: v2(32.94,60.36) v2(32.92,59.67) v2(32.95,59) v2(33.05,46.4) v2(33.15,45.7)
VL_L: length 45.2
  TOP w0.3: C34.1 49,20.5 v2(48.62,20.88) 48.35,21.15 Q4.4 Q4.8 47.19,21.07 R43.2
  TOP w0.4: v2(37,36.65) 34.51,36.65 33.81,35.95 U2.8
  TOP w0.5: C28.1 37.15,31 v2(37.2,31.05) ; 35.95,20.1 38.3,20.1 39.73,18.67 46.77,18.67 47.19,19.09 R43.2
  TOP w0.6: C46.1 35.95,20.1 ; TP19.1 32,19 R57.2
  TOP w1: J5.1 42.25,13.8 35.95,20.1
  BOTTOM w0.4: v2(37,36.65) 37.2,36.45 v2(37.2,31.05)
  BOTTOM w1: v2(33,24.53) v2(33,23.63) v2(33,22.75)
  vias: v2(32.59,39) v2(32.59,38.23) v2(32.79,37.47)
N16435324: length 11.3
  TOP w0.8: U3.1 12.25,72 C37.1 12.75,70.12 FB1.2
N16435348: length 11.2
  TOP w0.8: FB2.2 14.25,69.88 C37.2 14.79,72.04 U3.2
N16435442: length 3.8
  TOP w0.8: R47.2 12.75,64.28 C38.1 12.25,66.5 FB1.1
N16436009: length 5.9
  TOP w0.6: D9.1 35.25,76.69 R46.2 35.56,77.76 36.25,78.45 Q5.1 38.23,78.75 R45.1
N16436033: length 20.9
  TOP w0.4: D10.2 38.44,70.25 R50.1
  TOP w0.6: U3.5 23.83,79.08 24.67,79.08 30.2,73.55 30.2,72.7 32.66,70.25 C39.1 35.23,70.25 R49.1 36.98,70.28 D10.2
N16436085: length 2
  TOP w0.6: R46.1 37,76.44 D8.1
N16436375: length 18.4
  TOP w0.6: U3.7 32.74,75.25 C35.2 33.5,79.9 33.15,80.25 Q5.2 38.23,80.25 R45.2
N16436395: length 1.6
  TOP w0.4: 36.25,81.8 36.3,81.75 ; 36.3,81.75 R44.1 ; 36.3,81.75 Q5.3
N16440193: length 3
  TOP w1: R2.2 R1.1
N16449698: length 21.5
  TOP w0.6: D3.1 36.59,48.37 v2(36.45,48.51) 36.21,48.75 C17.2 34.98,48.75 33.91,49.83 U1.2 ; v2(37,61.75) R16.2
  BOTTOM w0.4: v2(36.45,48.51) 36.45,49.1 35.85,49.7 35.85,52.6 36.4,53.15 36.4,56.65 35.95,57.1 35.95,58 35.45,58.5 35.45,61.05 36.15,61.75 v2(37,61.75)
N16450369: length 7.9
  TOP w0.6: 35.56,56.6 33.87,54.91 U1.6
  TOP w0.8: 35.56,56.6 37.26,56.6 37.91,57.25 D1.1
N16454045: length 22
  TOP w0.6: v2(37.9,39.3) 38.6,38.6 R37.1 ; U2.2 33.91,28.32 34.98,27.25 C31.2 36,27.25 36.32,26.92 v2(36.5,26.92) 36.55,26.87 D7.1
  BOTTOM w0.4: v2(36.5,26.92) 35.6,27.82 35.6,30.9 36.45,31.75 36.45,35.95 35.75,36.65 35.75,38.62 36.53,39.4 37.8,39.4 v2(37.9,39.3)
N16454073: length 2.1
  TOP w0.6: R37.2 42.55,38.6 D6.2
N16454215: length 8.2
  TOP w0.4: U2.6 33.81,33.41 35.4,35 ; D5.1 39.85,35.8
  TOP w0.7: 35.4,35 36.8,35
  TOP w0.9: D5.1 39.35,35.8 37.6,35.8 36.8,35
N16459777: length 5.1
  TOP w0.5: U2.10 21.7,34.67 21.52,34.5 C25.2 20.43,34.58 18.55,34.58
N16461917: length 6.3
  TOP w0.4: U1.14 21.85,51.09 21.72,51.23 R12.1 20.73,51.25 C15.2 18.98,51.23 R18.2
N16462279: length 5.1
  TOP w0.6: 18.55,56.08 18.62,56 C11.2 21.18,56 21.35,56.17 U1.10
N16462299: length 6.4
  TOP w0.4: U1.11 21.65,54.91 21.47,54.73 R9.2 18.62,54.73 C12.2 17.18,54.75 R7.2
N16604212: length 2.7
  TOP w0.3: R42.2 45.04,21.1 Q4.3 46.38,19.82 R43.1
N16606674: length 2.8
  TOP w0.3: R24.2 44.56,45.1 Q3.3 45.88,43.81 R25.1
N16609193: length 3.8
  TOP w0.25: R60.2 20.7,65.22 U5.5 21.39,66.8 R59.1
N16609281: length 4.1
  TOP w0.25: R61.2 17,66.3 17.65,66.95 18.65,66.95 U5.4 18.8,65.22 R60.1
N16609329: length 3.3
  TOP w0.25: R61.1 R62.1 JR1.2
N16617325: length 2.2
  TOP w0.6: R16.1 D2.2
N16620609: length 1.6
  TOP w0.23: R38.2 C27.1
N16623492: length 1.6
  TOP w0.25: R14.2 C13.1
N16630507: length 2.9
  TOP w1: D4.2 34.33,42.8 R23.1
N16647913: length 6.3
  TOP w0.4: R30.2 17.27,33.25 C26.2 19.02,33.23 R32.2 20.68,33.41 U2.11
N16647969: length 6.3
  TOP w0.4: U2.14 20.88,29.59 R36.1 20.73,29.75 C29.2 18.98,29.73 R39.2
N16659533: length 15.2
  TOP w0.6: R52.2 33.27,10.03 Q6.2 33.25,6.9 ; R52.2 31.05,12 28.48,9.43 28.48,8.74 U4.7 ; R52.2 33.25,12.03 33.25,12.95 33,13.2 C41.2
N16659557: length 6.1
  TOP w0.5: R51.1 31,9.25 Q6.3
N16659577: length 6
  TOP w0.6: 34.75,11.98 R52.1 34.73,12.95 34.75,12.97 34.75,13.1 35,13.35 D12.1 ; 34.75,11.98 34.8,11.93 35.12,11.93 35.49,11.56 R53.2 ; 34.75,11.98 Q6.1
N16659585: length 7.3
  TOP w0.6: R53.1 37,13.19 37,16.15 35.65,17.5 D11.1
N16659631: length 3.9
  TOP w0.8: R54.2 C43.1 11.95,15.97 FB3.1
N16659643: length 6.6
  TOP w0.8: FB3.2 11.85,13 C44.1 12.35,11.53 12.25,11.43 U4.1
N16659681: length 6.9
  TOP w0.8: FB4.2 14.1,13.2 13.85,12.95 C44.2 13.85,10.15 14.79,9.21 U4.2
N16659765: length 14.6
  TOP w0.6: R57.1 30.06,18.61 29,17.55 D13.2 29.02,17.48 R56.1 29,15.72 C45.1 28.66,14 U4.5
N16681015: length 4.3
  TOP w0.23: Q4.6 47.59,22.4 Q4.7 46.89,22.4 Q4.1
  TOP w0.25: Q4.6 Q4.5 ; Q4.2 Q4.1
  TOP w0.3: R41.1 48.91,22.4 Q4.6
N16681091: length 4.2
  TOP w0.25: Q3.6 Q3.5 47.04,45.75 Q3.7 46.44,45.75 Q3.2 Q3.1
  TOP w0.3: R21.1 48.41,46.4 Q3.6
N16706392: length 14.6
  TOP w0.5: C28.2 34.95,31 34.7,30.75
  TOP w0.6: 34.59,30.86 U2.4
  TOP w0.8: 34.59,30.86 34.7,30.75 34.7,30.49 35.05,30.14 36.41,30.14 37.45,29.09 43,29.09 44.09,28 R33.1
N16706479: length 13.5
  TOP w0.5: C14.2 34.95,52.5 34.7,52.25
  TOP w0.6: 34.59,52.37 U1.4
  TOP w0.8: R10.1 42.93,49.25 41.83,50.35 39.13,50.35 39.13,50.35 38.15,50.35 36.87,51.63 35.93,51.63 35.92,51.64 35.05,51.64 34.7,51.99 34.7,52.25 34.59,52.37
N16716595: length 10.5
  TOP w0.6: U3.6 31.56,73.89 R48.1
N16716713: length 6.5
  TOP w0.6: R55.1 28.44,11.88 28.44,11.24 U4.6
N164429221: length 1.8
  TOP w0.25: LED2.2 R19.1
N164432121: length 1.8
  TOP w0.25: LED4.2 R40.1
N164593681: length 1.8
  TOP w0.25: LED3.2 R28.1
N164621091: length 1.8
  TOP w0.25: LED1.2 R4.1

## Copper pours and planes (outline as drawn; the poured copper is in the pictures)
GND_SIGNAL on TOP (solid shape): 22.6,59.15 23.75,59.15 24,58.9 24,57.1 20.15,57.1 20,57.25 20,59.95 20.5,60.45 21.3,60.45
GND_SIGNAL on TOP (solid shape): 22.6,37.65 23.9,37.65 24.55,37 24.55,35.65 24.5,35.6 20.15,35.6 20,35.75 20,38.45 20.5,38.95 21.3,38.95
GND_SIGNAL on TOP (solid shape): 23.7,45.9 23.15,45.35 19.7,45.35 19.55,45.5 19.55,46.6 19.6,46.65 21.7,46.65 21.9,46.85 21.9,48.35 22.4,48.85 23.7,48.85
GND_SIGNAL on TOP (solid shape): 23.8,24.65 23.1,23.95 19.55,23.95 19.3,24.2 19.3,25.1 19.45,25.25 21.65,25.25 21.85,25.45 21.85,26.8 22.4,27.35 23.8,27.35
GND_SIGNAL on TOP: 18.25,73.3 18.3,73.3 23.5,68.1 23.5,24.2 15.8,16.5 15.8,0.75 8.3,0.75 0.7,8.35 0.7,75.75 6,81.05 6,83.25 16,83.25 16.25,83 16.25,75.3 ; 4 cut-outs
GND_SIGNAL on BOTTOM: 18.25,73.3 18.3,73.3 23.5,68.1 23.5,25.25 22.02,23.77 22.02,22.73 15.8,16.5 15.8,0.75 8.3,0.75 0.7,8.35 0.7,80.3 0.75,80.25 0.75,81 3,83.25 15,83.25 15.75,82.5 15.75,75.8
GNDISO_H on TOP (solid shape): 37.95,59.85 37.95,58.9 37.85,58.8 36.02,58.8 35.65,58.8 35.5,58.65 35.2,58.65 35.1,58.75 35.1,60.85 35.2,60.95 36.85,60.95
GNDISO_H on TOP: 36.7,47.75 36.96,47.5 36.96,46.48 36.7,46.23 34.8,46.23 34.54,46.48 34.54,47.5 34.8,47.75
GNDISO_H on TOP: 38.65,76 41.35,76 41.35,72.4 41,72.05 38.15,72.05 37.4,71.3 32.5,71.3 32.2,71.6 32.2,73.85 32.5,74.15 34.4,74.15 34.7,73.85 37.4,73.85 38.15,74.6 38.15,75.5
GNDISO_H on BOTTOM: 45.15,78.15 51.05,78.15 51.4,77.8 51.4,69.65 47.15,65.4 47.15,61.2 48.91,59.44 49.78,59.44 52.07,57.15 52.07,54.61 54,52.68 54,44.5 53.5,44 42.48,44 40.25,46.23 35.75,46.23 35.6,46.38 35.6,48 36.2,48.6 36.2,60.35 36.6,60.75 41.8,60.75 42.8,61.75 42.8,66.75 43.3,67.25 43.3,76.3
GNDISO_L on TOP (solid shape): 37.2,25.65 37.2,22.9 36.55,22.25 34.9,22.25 34.7,22.45 34.7,25.95 36.9,25.95
GNDISO_L on TOP (solid shape): 37.95,38.4 37.95,37.45 37.85,37.35 36.02,37.35 35.75,37.35 35.66,37.26 35.61,37.23 35.57,37.2 35.3,37.2 35.2,37.3 35.2,39.5 36.85,39.5
GNDISO_L on TOP: 29.7,12.8 29.7,12.2 30.3,12.2 30.8,12.7 31.95,12.7 32.15,12.9 32.15,15 32.35,15.2 35.5,15.2 35.8,15.5 35.8,16.25 35.5,16.55 33.35,16.55 33.35,17.9 33.25,18 30.07,18 30.07,13.18
GNDISO_L on BOTTOM: 45.4,30.5 45.4,34.1 43.4,36.1 42.4,36.1 42,36.5 42,38.48 37.85,38.48 37.33,39 36.15,39 34.65,37.5 34.65,21.05 31.3,17.7 31.3,10.45 36.4,5.35 48.6,5.35 54,10.75 54,28 47.9,28
GNDPWR on TOP: 97.25,33.3 115.82,33.3 115.82,21.55 97.25,21.55
GNDPWR on TOP: 54.5,28 54.5,21.75 58.25,18 115.5,18 115.75,18.25 115.75,35.75 79.25,35.75 71.5,28
GNDPWR on TOP: 55.75,82.5 55.25,82 55.25,79 56.9,79 58.4,80.5 73.25,80.5 77.75,76 94,76 94.85,76.85 94.85,80.4 92.75,82.5
GNDPWR on BOTTOM: 58.25,18 54.85,21.4 54.85,27.99 67.32,27.99 71.35,31.99 71.35,80.95 72.9,82.5 92.75,82.5 94.85,80.4 94.85,39.65 98.75,35.75 115.82,35.75 115.82,18.32 115.5,18
G_HS on TOP: 45.3,51.8 45.3,47.2 45.5,47 47.8,47 47.95,47.15 47.95,48.3 48.3,48.65 52.75,48.65 52.9,48.8 52.9,52.2 48.3,52.2 47.9,51.8
G_LS on TOP: 45.05,28.85 45.05,27.95 45.25,27.75 45.25,25.7 44.65,25.1 44.65,24.3 44.75,24.2 45.5,24.2 45.6,24.1 45.6,23.55 45.9,23.25 48.25,23.25 49.2,24.2 53.15,24.2 53.25,24.3 53.25,28.2 53.2,28.25 47.65,28.25 47.05,28.85
HV on TOP: 115.82,69.49 115.82,59.5 100.52,59.5 96.32,55.3 48.4,55.3 48.4,59.85 47.65,60.6 44.95,60.6 44.7,60.85 44.7,65.95 48.24,69.49
HV on BOTTOM: 103,69.49 115.82,69.49 115.82,59.5 103,59.5
Net_4 on TOP (solid shape): 107.05,6.82 105.52,6.82 105.52,7.96 107.05,7.96
Net_4 on TOP (solid shape): 107.1,11.37 105.57,11.37 105.57,12.51 107.1,12.51
Net_5 on TOP (solid shape): 107.05,8.97 105.52,8.97 105.52,10.12 107.05,10.12
Net_5 on TOP (solid shape): 107.1,13.53 105.57,13.53 105.57,14.67 107.1,14.67
OUT on TOP: 69.35,31.35 79,41 106.25,41 106.25,51 67,51 65.75,52.25 54.5,52.25 54.5,42.4 54.1,42 45.75,42 45.5,41.75 45.5,39.25 48.5,36.25 48.5,31.75 48.9,31.35
OUT on TOP: 93.5,51 115.82,51 115.82,41 93.5,41
OUT on BOTTOM: 68.25,49.76 68.25,34.95 64.55,31.25 49,31.25 48.5,31.75 48.5,36.25 45.5,39.25 45.5,41.75 45.75,42 54.1,42 54.5,42.4 54.5,52.25 65.75,52.25
VL_H on TOP: 33.78,58.3 33.78,57.28 32.13,57.28 32.13,57.66 33.27,57.66 33.27,58.55 32.26,58.55 32.13,58.67 32.13,60.71 32.26,60.83 34.38,60.83 34.4,60.85 34.4,58.75 33.95,58.3
VL_H on TOP: 33.91,48.77 33.91,46.6 34.4,46.11 34.4,45.5 34.24,45.34 33,45.34 32.8,45.54 32.8,46.6 33.15,46.95 33.15,48.26 32.13,48.26 32.13,48.77
VL_H on BOTTOM: 33.25,55.45 33.25,58.4 33.45,58.6 33.45,60.95 32.95,61.45 32.15,61.45 32,61.3 32,45.59 32.26,45.34 34.24,45.34 34.4,45.5 34.4,54.3
VL_L on TOP: 33.91,27.3 33.91,21.72 34.92,20.7 36.32,20.7 36.32,19.43 32.13,19.43 32.13,25.78 32.26,25.91 33.27,25.91 33.27,26.8 32.13,26.8 32.13,27.3
VL_L on TOP: 33.91,36.85 33.91,35.69 32.13,35.69 32.13,36.2 33.27,36.2 33.27,37.08 32.26,37.08 32.13,37.21 32.13,39.12 32.38,39.37 34.48,39.37 34.5,39.35 34.5,37.25 34.31,37.25
VL_L on BOTTOM: 33.25,33.95 33.25,36.9 33.45,37.1 33.45,39.35 33.4,39.4 32.3,39.4 32,39.1 32,24.86 32.15,23.92 32.15,22.2 32.25,22.1 33.5,22.1 33.8,22.4 33.8,26.4 33.4,26.8 33.4,33.8
N16436375 on TOP (solid shape): 35.74,80.55 36.35,80.55 36.35,79.95 35.74,79.95 35.06,79.25 32.61,79.25 32.61,81.25 35.06,81.25
N16450369 on TOP: 38.61,57.72 41.15,57.72 41.27,57.59 41.27,54.23 38.73,54.23 38.73,56.64 38.48,56.9 38.48,57.59
N16450393 on TOP: 44.83,54.23 42.16,54.23 42.16,57.59 42.29,57.72 43.69,57.72 43.69,57.02 44.83,55.88
N16454215 on TOP: 41.27,32.77 41.27,34.98 40.05,36.2 38.67,36.2 38.61,36.13 38.61,35.37 38.73,35.24 38.73,32.77
N16454235 on TOP: 43.69,36.2 43.69,35.62 44.83,34.48 44.83,32.77 42.16,32.77 42.16,36.07 42.29,36.2
N16636383 on TOP: 58.82,76.27 58.82,73.42 65.68,73.42 65.68,76.27
N16636469 on TOP: 66.31,76.27 66.31,73.42 73.17,73.42 73.17,76.27
N16659533 on TOP (solid shape): 33.55,9.49 34.25,8.81 34.25,6.36 32.25,6.36 32.25,8.81 32.95,9.49 32.95,10.1 33.55,10.1

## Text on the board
Ref Des/Silkscreen Top: I | S | Version: | DIAG | RST | RDY | IN+HS | IN-HS | IN+LS | IN-LS | H | L | GND | VDD | VAUX | FOR EVALUATION ONLY | Rev.2 | EVLSTGAP3S6
XSECTION_CHART: *  SURFACE - AIR 0 MM | L1 TOP CONDUCTOR - 1OZ_COPPER 0.035 MM | *  DIELECTRIC - FR-4 1.55 MM | L2 BOTTOM CONDUCTOR - 1OZ_COPPER 0.035 MM | DESIGN CROSS SECTION CHART | ___________________________ | TOTAL THICKNESS 1.62 MM | 1-2 | PIANO DI MONTAGGIO
PAGE_OUTLINE: 1:1 | D.PANZERI | DRILLING AND PROFILING | EVLSTGAP3S6 | STGAP3S6 | 2.0
User.45: FIGURE | SIZE | 0.25 | 0.3 | 0.8 | 0.9 | 1.0 | 1.1 | 2.1 | 3.2 | DRILL CHART: TOP to BOTTOM | ALL UNITS ARE IN MILLIMETERS | PLATED | QTY | 107 | 236 | 10 | 29 | 2 | 5 | 7 | 2:1 | "C" holes must remain OPEN after solder phase | OPEN after solder phase. | When THT components aren't mounted your holes must remain | ASSEMBLY DRAWING
